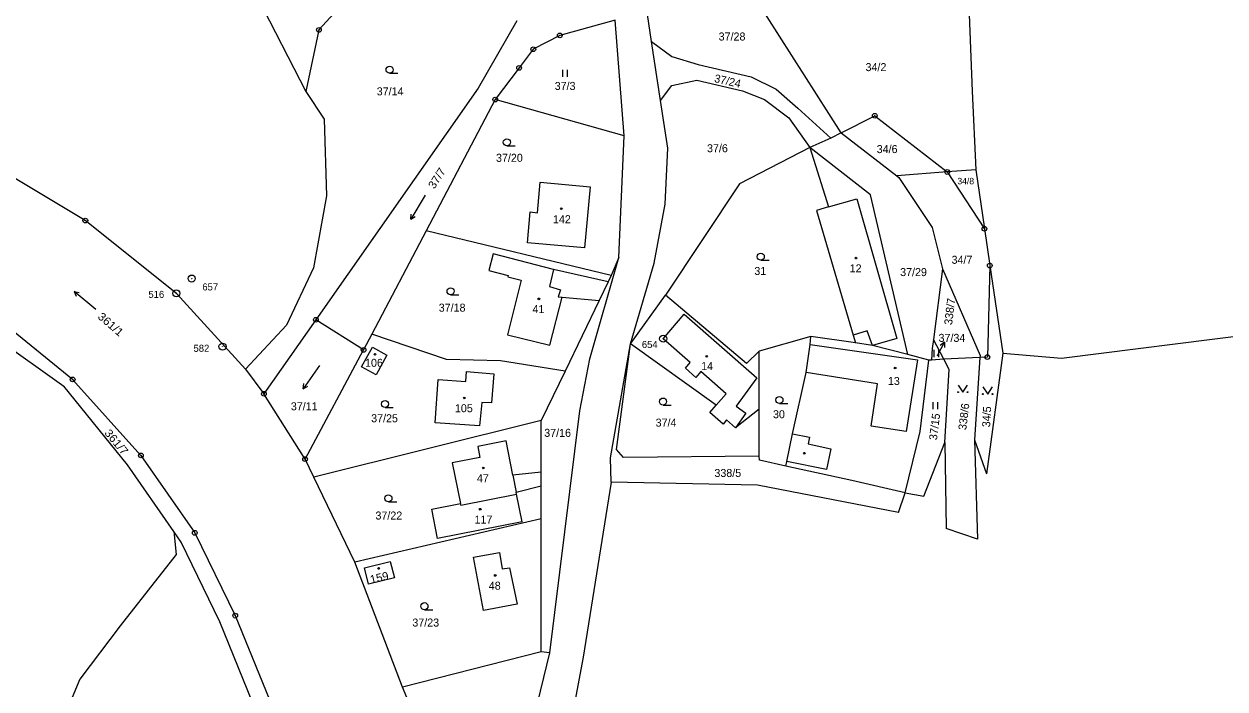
# Model space of a CAD drawing. Extents: x -645290 to -643454, y -1064771 to -1062356.
# Drawn here: x -644666.5 to -644411.4, y -1063973.1 to -1063831.9 of the extents above; entities that cross this region are included whole.
import ezdxf
from ezdxf.enums import TextEntityAlignment as Align

# ---------------------------------------------------------------- set-up
doc = ezdxf.new("R2010")
doc.units = 0
doc.header["$LTSCALE"] = 0.68
for name, color, linetype, lineweight in [('1', 7, 'Continuous', 25), ('3', 7, 'Continuous', 25), ('4', 7, 'Continuous', 13), ('5', 7, 'Continuous', 25), ('7', 7, 'Continuous', 13), ('8', 7, 'Continuous', 25)]:
    doc.layers.add(name, color=color, linetype=linetype, lineweight=lineweight)
doc.layers.add('2', color=7, linetype='Continuous')

msp = doc.modelspace()

# ---------------------------------------------------------------- linework, layer by layer
at = {"layer": '1'}
for p, q in [((-644575.96, -1063802.49), (-644603.81, -1063833.16)), ((-644627.33, -1063805.69), (-644606.6, -1063846.26)), ((-644492.88, -1063855.02), (-644514.22, -1063821.58)), ((-644466.06, -1063820.7), (-644465.03, -1063846.16)), ((-644533.14, -1063835.63), (-644534.01, -1063829.87)), ((-644561.79, -1063831.23), (-644569.98, -1063845.53)), ((-644540.88, -1063831.09), (-644552.65, -1063834.34)), ((-644538.96, -1063855.68), (-644540.88, -1063831.09)), ((-644603.81, -1063833.16), (-644606.6, -1063846.26)), ((-644552.65, -1063834.34), (-644558.27, -1063837.27)), ((-644558.27, -1063837.27), (-644561.29, -1063841.21)), ((-644531.25, -1063848.13), (-644533.14, -1063835.63)), ((-644533.14, -1063835.63), (-644528.83, -1063838.81)), ((-644528.83, -1063838.81), (-644523.29, -1063840.5)), ((-644561.29, -1063841.21), (-644566.37, -1063847.94)), ((-644523.29, -1063840.5), (-644512.02, -1063843.09)), ((-644531.25, -1063848.13), (-644528.83, -1063844.98)), ((-644528.83, -1063844.98), (-644523.54, -1063843.86)), ((-644523.54, -1063843.86), (-644513.81, -1063846.11)), ((-644512.02, -1063843.09), (-644506.66, -1063845.77)), ((-644606.6, -1063846.26), (-644602.72, -1063852.13)), ((-644569.98, -1063845.53), (-644604.46, -1063894.71)), ((-644566.37, -1063847.94), (-644581.03, -1063875.82)), ((-644538.96, -1063855.68), (-644566.37, -1063847.94)), ((-644513.81, -1063846.11), (-644509.15, -1063847.9)), ((-644509.15, -1063847.9), (-644504.01, -1063851.81)), ((-644506.66, -1063845.77), (-644502.07, -1063849.8)), ((-644465.03, -1063846.16), (-644464.3, -1063862.86)), ((-644529.72, -1063858.26), (-644531.25, -1063848.13)), ((-644502.07, -1063849.8), (-644495.11, -1063856.11)), ((-644602.72, -1063852.13), (-644602.19, -1063868.36)), ((-644504.01, -1063851.81), (-644499.57, -1063858.15)), ((-644540.1, -1063881.52), (-644538.96, -1063855.68)), ((-644492.88, -1063855.02), (-644495.11, -1063856.11)), ((-644492.88, -1063855.02), (-644481.08, -1063864.17)), ((-644499.57, -1063858.15), (-644514.49, -1063865.83)), ((-644495.11, -1063856.11), (-644499.57, -1063858.15)), ((-644486.65, -1063868.19), (-644499.57, -1063858.15)), ((-644499.57, -1063858.15), (-644495.55, -1063870.76)), ((-644530.24, -1063870.17), (-644529.72, -1063858.26)), ((-644653.43, -1063873.64), (-644671.61, -1063862.81)), ((-644470.36, -1063863.33), (-644481.08, -1063864.17)), ((-644464.3, -1063862.86), (-644470.36, -1063863.33)), ((-644470.36, -1063863.33), (-644462.46, -1063875.37)), ((-644464.3, -1063862.86), (-644462.46, -1063875.37)), ((-644556.8, -1063865.48), (-644546.19, -1063866.48)), ((-644514.49, -1063865.83), (-644530.22, -1063889.47)), ((-644602.19, -1063868.36), (-644604.98, -1063883.66)), ((-644546.19, -1063866.48), (-644547.38, -1063879.46)), ((-644478.75, -1063902.1), (-644486.65, -1063868.19)), ((-644532.59, -1063882.67), (-644530.24, -1063870.17)), ((-644495.55, -1063870.76), (-644498.09, -1063871.5)), ((-644559.52, -1063878.34), (-644558.91, -1063871.8)), ((-644498.09, -1063871.5), (-644490.36, -1063897.96)), ((-644634.09, -1063889.1), (-644653.43, -1063873.64)), ((-644581.03, -1063875.82), (-644592.55, -1063897.74)), ((-644541.7, -1063885.33), (-644581.03, -1063875.82)), ((-644462.46, -1063875.37), (-644461.31, -1063883.19)), ((-644547.38, -1063879.46), (-644559.52, -1063878.34)), ((-644566.81, -1063880.73), (-644567.71, -1063884.25)), ((-644553.98, -1063884.01), (-644566.81, -1063880.73)), ((-644604.98, -1063883.66), (-644610.67, -1063895.83)), ((-644546.25, -1063903.03), (-644540.1, -1063881.52)), ((-644540.1, -1063881.52), (-644541.7, -1063885.33)), ((-644537.63, -1063899.85), (-644532.59, -1063882.67)), ((-644461.31, -1063883.19), (-644458.57, -1063901.82)), ((-644567.71, -1063884.25), (-644563.64, -1063885.29)), ((-644563.64, -1063885.29), (-644563.71, -1063885.58)), ((-644563.71, -1063885.58), (-644560.87, -1063886.32)), ((-644542.36, -1063886.68), (-644553.98, -1063884.01)), ((-644541.7, -1063885.33), (-644542.36, -1063886.68)), ((-644471.38, -1063883.92), (-644473.27, -1063898.87)), ((-644471.38, -1063883.92), (-644463.37, -1063902.3)), ((-644560.87, -1063886.32), (-644563.73, -1063897.9)), ((-644542.36, -1063886.68), (-644544.27, -1063890.64)), ((-644619.42, -1063905.23), (-644634.09, -1063889.1)), ((-644554.79, -1063900.11), (-644552.17, -1063889.9)), ((-644552.17, -1063889.9), (-644544.27, -1063890.64)), ((-644544.27, -1063890.64), (-644551.54, -1063905.66)), ((-644537.63, -1063899.85), (-644530.22, -1063889.47)), ((-644512.98, -1063904.01), (-644530.22, -1063889.47)), ((-644656.12, -1063907.37), (-644671.86, -1063894.68)), ((-644610.67, -1063895.83), (-644619.42, -1063905.23)), ((-644604.46, -1063894.71), (-644615.5, -1063910.43)), ((-644594.32, -1063901.11), (-644604.46, -1063894.71)), ((-644673.62, -1063897.69), (-644657.97, -1063908.8)), ((-644592.55, -1063897.74), (-644594.32, -1063901.11)), ((-644576.74, -1063903.12), (-644592.55, -1063897.74)), ((-644563.73, -1063897.9), (-644554.79, -1063900.11)), ((-644499.35, -1063898.27), (-644510.33, -1063901.35)), ((-644499.47, -1063899.93), (-644499.35, -1063898.27)), ((-644489.87, -1063899.62), (-644499.35, -1063898.27)), ((-644490.36, -1063897.96), (-644489.87, -1063899.62)), ((-644471.09, -1063903.09), (-644473.27, -1063898.87)), ((-644446.1, -1063902.87), (-644404.58, -1063897.62)), ((-644606.74, -1063924.29), (-644594.32, -1063901.11)), ((-644594.74, -1063904.69), (-644592.43, -1063900.51)), ((-644592.43, -1063900.51), (-644589.37, -1063902.2)), ((-644541.87, -1063924.06), (-644537.63, -1063899.85)), ((-644540.57, -1063922.23), (-644537.63, -1063899.85)), ((-644519.44, -1063912.83), (-644537.63, -1063899.85)), ((-644510.33, -1063901.35), (-644512.98, -1063904.01)), ((-644510.33, -1063913.68), (-644510.33, -1063901.35)), ((-644500.33, -1063905.88), (-644499.47, -1063899.93)), ((-644486.2, -1063900.15), (-644489.87, -1063899.62)), ((-644478.75, -1063902.1), (-644486.2, -1063900.15)), ((-644589.37, -1063902.2), (-644591.68, -1063906.38)), ((-644565.21, -1063903.46), (-644576.74, -1063903.12)), ((-644551.54, -1063905.66), (-644565.21, -1063903.46)), ((-644548.36, -1063914.06), (-644546.25, -1063903.03)), ((-644474.26, -1063903.27), (-644478.75, -1063902.1)), ((-644476.07, -1063918.47), (-644474.26, -1063903.27)), ((-644473.68, -1063903.29), (-644474.26, -1063903.27)), ((-644471.09, -1063903.09), (-644473.68, -1063903.29)), ((-644463.4, -1063902.71), (-644471.09, -1063903.09)), ((-644469.95, -1063905.28), (-644471.09, -1063903.09)), ((-644463.4, -1063902.71), (-644464.59, -1063920.21)), ((-644463.37, -1063902.3), (-644463.4, -1063902.71)), ((-644458.57, -1063901.82), (-644462.03, -1063927.42)), ((-644458.57, -1063901.82), (-644446.1, -1063902.87)), ((-644619.42, -1063905.23), (-644615.5, -1063910.43)), ((-644591.68, -1063906.38), (-644594.74, -1063904.69)), ((-644572.63, -1063907.84), (-644572.48, -1063905.69)), ((-644572.48, -1063905.69), (-644566.68, -1063906.21)), ((-644566.68, -1063906.21), (-644567.15, -1063912.37)), ((-644551.54, -1063905.66), (-644556.6, -1063916.11)), ((-644503.22, -1063918.97), (-644500.33, -1063905.88)), ((-644470.87, -1063920.76), (-644469.95, -1063905.28)), ((-644644.48, -1063925.51), (-644657.97, -1063908.8)), ((-644641.61, -1063923.51), (-644656.12, -1063907.37)), ((-644579.14, -1063916.6), (-644578.49, -1063907.42)), ((-644578.49, -1063907.42), (-644572.63, -1063907.84)), ((-644606.74, -1063924.29), (-644615.5, -1063910.43)), ((-644569.19, -1063912.29), (-644569.69, -1063917.27)), ((-644567.15, -1063912.37), (-644569.19, -1063912.29)), ((-644554.73, -1063965.42), (-644548.36, -1063914.06)), ((-644520.8, -1063914.38), (-644519.44, -1063912.83)), ((-644510.33, -1063913.68), (-644515.32, -1063917.63)), ((-644510.33, -1063923.68), (-644510.33, -1063913.68)), ((-644556.6, -1063916.11), (-644604.88, -1063928.15)), ((-644569.69, -1063917.27), (-644579.14, -1063916.6)), ((-644556.6, -1063927.09), (-644556.6, -1063916.11)), ((-644517.94, -1063916.9), (-644520.8, -1063914.38)), ((-644517.25, -1063915.94), (-644517.94, -1063916.9)), ((-644515.32, -1063917.63), (-644517.25, -1063915.94)), ((-644504.42, -1063924.79), (-644503.22, -1063918.97)), ((-644479.27, -1063931.46), (-644476.07, -1063918.47)), ((-644564.06, -1063920.45), (-644570.04, -1063921.65)), ((-644570.04, -1063921.65), (-644569.6, -1063923.97)), ((-644562.63, -1063927.7), (-644564.06, -1063920.45)), ((-644475.33, -1063932.16), (-644470.87, -1063920.76)), ((-644470.87, -1063920.76), (-644470.6, -1063939.03)), ((-644464.59, -1063920.21), (-644463.9, -1063941.3)), ((-644464.59, -1063920.21), (-644462.03, -1063927.42)), ((-644641.61, -1063923.51), (-644630.18, -1063939.96)), ((-644604.88, -1063928.15), (-644606.74, -1063924.29)), ((-644569.6, -1063923.97), (-644575.52, -1063925.08)), ((-644541.7, -1063929.17), (-644541.87, -1063924.06)), ((-644539.12, -1063923.94), (-644540.57, -1063922.23)), ((-644510.33, -1063923.68), (-644539.12, -1063923.94)), ((-644510.23, -1063924.55), (-644510.33, -1063923.68)), ((-644504.63, -1063925.77), (-644510.23, -1063924.55)), ((-644634.62, -1063939.7), (-644644.48, -1063925.51)), ((-644575.52, -1063925.08), (-644573.77, -1063933.74)), ((-644556.6, -1063927.09), (-644562.63, -1063927.7)), ((-644556.6, -1063929.98), (-644556.6, -1063927.09)), ((-644504.63, -1063925.77), (-644504.42, -1063924.79)), ((-644490.58, -1063928.84), (-644504.63, -1063925.77)), ((-644596.19, -1063946.17), (-644604.88, -1063928.15)), ((-644541.7, -1063929.17), (-644547.65, -1063966.35)), ((-644510.64, -1063929.86), (-644541.7, -1063929.17)), ((-644479.27, -1063931.46), (-644490.58, -1063928.84)), ((-644573.69, -1063934.11), (-644561.82, -1063931.77)), ((-644561.92, -1063931.3), (-644556.6, -1063929.98)), ((-644561.82, -1063931.77), (-644561.92, -1063931.3)), ((-644560.66, -1063937.63), (-644561.82, -1063931.77)), ((-644556.59, -1063937.01), (-644556.6, -1063929.98)), ((-644480.67, -1063935.62), (-644510.64, -1063929.86)), ((-644480.67, -1063935.62), (-644479.27, -1063931.46)), ((-644479.27, -1063931.46), (-644475.33, -1063932.16)), ((-644579.82, -1063934.92), (-644573.77, -1063933.74)), ((-644573.69, -1063934.11), (-644573.77, -1063933.74)), ((-644556.59, -1063937.01), (-644596.19, -1063946.17)), ((-644578.61, -1063941.13), (-644579.82, -1063934.92)), ((-644556.6, -1063965.23), (-644556.59, -1063937.01)), ((-644634.62, -1063939.7), (-644634.12, -1063944.59)), ((-644633.06, -1063941.95), (-644634.62, -1063939.7)), ((-644560.66, -1063937.63), (-644578.61, -1063941.13)), ((-644463.9, -1063941.3), (-644470.6, -1063939.03)), ((-644624.84, -1063958.87), (-644633.06, -1063941.95)), ((-644630.18, -1063939.96), (-644621.6, -1063957.55)), ((-644634.12, -1063944.59), (-644646.05, -1063959.71)), ((-644570.97, -1063945.16), (-644565.48, -1063944.11)), ((-644565.48, -1063944.11), (-644564.88, -1063947.62)), ((-644586.08, -1063972.72), (-644596.19, -1063946.17)), ((-644594.13, -1063947.4), (-644588.66, -1063946.07)), ((-644593.25, -1063950.83), (-644594.13, -1063947.4)), ((-644588.66, -1063946.07), (-644587.76, -1063949.55)), ((-644568.87, -1063956.42), (-644570.97, -1063945.16)), ((-644564.88, -1063947.62), (-644563.3, -1063947.42)), ((-644563.3, -1063947.42), (-644561.73, -1063955.08)), ((-644587.76, -1063949.55), (-644593.25, -1063950.83)), ((-644561.73, -1063955.08), (-644568.87, -1063956.42)), ((-644621.6, -1063957.55), (-644613.6, -1063977.09)), ((-644646.05, -1063959.71), (-644654.6, -1063971.04)), ((-644616.95, -1063978.39), (-644624.84, -1063958.87)), ((-644556.6, -1063965.23), (-644586.08, -1063972.72)), ((-644554.73, -1063965.42), (-644556.6, -1063965.23)), ((-644559.44, -1063984.36), (-644554.73, -1063965.42)), ((-644547.65, -1063966.35), (-644549.67, -1063976.91)), ((-644654.6, -1063971.04), (-644661.51, -1063987.36)), ((-644581.25, -1063984.25), (-644586.08, -1063972.72))]:
    msp.add_line(p, q, dxfattribs=at)
for points in [[(-644492.88, -1063855.02), (-644485.74, -1063851.39), (-644470.36, -1063863.33)], [(-644558.91, -1063871.8), (-644557.41, -1063871.98), (-644556.8, -1063865.48)], [(-644481.08, -1063864.17), (-644480.66, -1063864.49), (-644473.56, -1063875.12), (-644471.38, -1063883.92)], [(-644461.31, -1063883.19), (-644461.82, -1063902.63), (-644463.4, -1063902.71)], [(-644473.27, -1063898.87), (-644473.52, -1063900.81), (-644473.68, -1063903.29)]]:
    msp.add_lwpolyline(points, dxfattribs=at)
at = {"layer": '3'}
for p, q in [((-644588.803, -1063842.36), (-644587.053, -1063842.36)), ((-644552.011, -1063843.11), (-644552.011, -1063841.61)), ((-644551.01, -1063843.11), (-644551.01, -1063841.61)), ((-644563.893, -1063857.77), (-644562.143, -1063857.77)), ((-644584.301, -1063873.382), (-644584.228, -1063872.286)), ((-644509.953, -1063882.07), (-644508.203, -1063882.07)), ((-644655.786, -1063888.704), (-644654.715, -1063888.948)), ((-644575.853, -1063889.41), (-644574.103, -1063889.41)), ((-644473.141, -1063902.63), (-644473.141, -1063901.13)), ((-644472.14, -1063902.63), (-644472.14, -1063901.13)), ((-644607.158, -1063909.357), (-644607.008, -1063908.269)), ((-644589.763, -1063913.35), (-644588.013, -1063913.35)), ((-644530.713, -1063912.83), (-644528.963, -1063912.83)), ((-644505.993, -1063912.5), (-644504.243, -1063912.5)), ((-644473.331, -1063913.71), (-644473.331, -1063912.21)), ((-644472.33, -1063913.71), (-644472.33, -1063912.21)), ((-644589.043, -1063933.38), (-644587.293, -1063933.38)), ((-644581.393, -1063956.29), (-644579.643, -1063956.29))]:
    msp.add_line(p, q, dxfattribs=at)
for points in [[(-644581.211, -1063868.239), (-644584.301, -1063873.382), (-644583.368, -1063872.802)], [(-644651.189, -1063892.561), (-644655.786, -1063888.704), (-644655.36, -1063889.716)], [(-644603.716, -1063904.442), (-644607.158, -1063909.357), (-644606.186, -1063908.844)], [(-644468.04, -1063908.589), (-644467.04, -1063910.09), (-644466.04, -1063908.589)], [(-644462.76, -1063908.979), (-644461.76, -1063910.48), (-644460.76, -1063908.979)]]:
    msp.add_lwpolyline(points, dxfattribs=at)
for centre, radius in [((-644588.8029, -1063841.6098), 0.75), ((-644563.8929, -1063857.0198), 0.75), ((-644509.9529, -1063881.3198), 0.75), ((-644575.8529, -1063888.6598), 0.75), ((-644530.7129, -1063912.0798), 0.75), ((-644505.9929, -1063911.7498), 0.75), ((-644468.04, -1063910.0895), 0.1), ((-644466.04, -1063910.0895), 0.1), ((-644462.76, -1063910.4795), 0.1), ((-644460.76, -1063910.4795), 0.1), ((-644589.7629, -1063912.5998), 0.75), ((-644589.0429, -1063932.6298), 0.75), ((-644581.3929, -1063955.5398), 0.75)]:
    msp.add_circle(centre, radius, dxfattribs=at)
at = {"layer": '4'}
for p, q in [((-644495.55, -1063870.76), (-644489.54, -1063869.02)), ((-644489.54, -1063869.02), (-644481.08, -1063898.69)), ((-644553.98, -1063884.01), (-644554.81, -1063887.64)), ((-644554.81, -1063887.64), (-644552.52, -1063888.32)), ((-644552.52, -1063888.32), (-644552.96, -1063889.83)), ((-644552.96, -1063889.83), (-644552.17, -1063889.9)), ((-644530.69, -1063898.74), (-644526.21, -1063893.51)), ((-644526.21, -1063893.51), (-644510.8, -1063907.03)), ((-644524.97, -1063903.77), (-644530.69, -1063898.74)), ((-644487.37, -1063897.08), (-644490.36, -1063897.96)), ((-644486.2, -1063900.15), (-644487.37, -1063897.08)), ((-644481.08, -1063898.69), (-644486.2, -1063900.15)), ((-644499.47, -1063899.93), (-644476.69, -1063903.22)), ((-644525.98, -1063905.02), (-644524.97, -1063903.77)), ((-644476.69, -1063903.22), (-644479.06, -1063918.44)), ((-644523.77, -1063907), (-644525.98, -1063905.02)), ((-644522.72, -1063905.73), (-644523.77, -1063907)), ((-644517.32, -1063910.43), (-644522.72, -1063905.73)), ((-644485.14, -1063908.33), (-644500.33, -1063905.88)), ((-644510.8, -1063907.03), (-644515.15, -1063913.04)), ((-644486.51, -1063917.3), (-644485.14, -1063908.33)), ((-644519.44, -1063912.83), (-644517.32, -1063910.43)), ((-644515.15, -1063913.04), (-644513.11, -1063914.52)), ((-644513.11, -1063914.52), (-644515.32, -1063917.63)), ((-644503.22, -1063918.97), (-644499.6, -1063919.61)), ((-644479.06, -1063918.44), (-644486.51, -1063917.3)), ((-644499.6, -1063919.61), (-644499.92, -1063921.03)), ((-644499.92, -1063921.03), (-644495.06, -1063922.09)), ((-644495.06, -1063922.09), (-644496.01, -1063926.51)), ((-644496.01, -1063926.51), (-644504.42, -1063924.79)), ((-644562.63, -1063927.7), (-644561.92, -1063931.3))]:
    msp.add_line(p, q, dxfattribs=at)
at = {"layer": '5'}
for centre in [(-644552.3368, -1063871.1192), (-644489.7268, -1063881.6192), (-644557.0968, -1063890.2692), (-644591.8868, -1063902.0392), (-644521.4368, -1063902.4692), (-644481.4168, -1063904.9692), (-644572.9368, -1063911.3192), (-644500.7168, -1063923.0492), (-644568.8968, -1063926.1892), (-644569.5568, -1063934.9492), (-644591.1368, -1063947.5192), (-644566.3668, -1063949.0092)]:
    msp.add_circle(centre, 0.175, dxfattribs=at)
at = {"layer": '7'}
msp.add_line((-644470.911, -1063899.5), (-644471.823, -1063900.149), dxfattribs=at)
msp.add_lwpolyline([(-644472.44, -1063902.37), (-644472.32, -1063902.15), (-644470.911, -1063899.5), (-644470.939, -1063900.62)], dxfattribs=at)
at = {"layer": '8'}
for centre, radius in [((-644603.81, -1063833.1599), 0.5), ((-644603.81, -1063833.1599), 0.0303), ((-644552.65, -1063834.3399), 0.5), ((-644552.65, -1063834.3399), 0.0303), ((-644558.27, -1063837.2699), 0.5), ((-644558.27, -1063837.2699), 0.0303), ((-644561.29, -1063841.2099), 0.5), ((-644561.29, -1063841.2099), 0.0303), ((-644566.37, -1063847.9399), 0.5), ((-644566.37, -1063847.9399), 0.0303), ((-644485.74, -1063851.3899), 0.5), ((-644485.74, -1063851.3899), 0.0303), ((-644470.36, -1063863.3299), 0.5), ((-644470.36, -1063863.3299), 0.0303), ((-644653.43, -1063873.6399), 0.5), ((-644653.43, -1063873.6399), 0.0303), ((-644462.46, -1063875.3699), 0.5), ((-644462.46, -1063875.3699), 0.0303), ((-644461.31, -1063883.1899), 0.5), ((-644461.31, -1063883.1899), 0.0303), ((-644630.83, -1063885.9598), 0.75), ((-644630.83, -1063885.9598), 0.03), ((-644634.09, -1063889.0998), 0.75), ((-644634.09, -1063889.0998), 0.03), ((-644604.46, -1063894.7099), 0.5), ((-644604.46, -1063894.7099), 0.0303), ((-644530.69, -1063898.7398), 0.75), ((-644530.69, -1063898.7398), 0.03), ((-644624.29, -1063900.4098), 0.75), ((-644624.29, -1063900.4098), 0.03), ((-644594.32, -1063901.1099), 0.5), ((-644594.32, -1063901.1099), 0.0303), ((-644461.82, -1063902.6299), 0.5), ((-644461.82, -1063902.6299), 0.0303), ((-644656.12, -1063907.3699), 0.5), ((-644656.12, -1063907.3699), 0.0303), ((-644615.5, -1063910.4299), 0.5), ((-644615.5, -1063910.4299), 0.0303), ((-644641.61, -1063923.5099), 0.5), ((-644641.61, -1063923.5099), 0.0303), ((-644606.74, -1063924.2899), 0.5), ((-644606.74, -1063924.2899), 0.0303), ((-644630.18, -1063939.9599), 0.5), ((-644630.18, -1063939.9599), 0.0303), ((-644621.6, -1063957.5499), 0.5), ((-644621.6, -1063957.5499), 0.0303)]:
    msp.add_circle(centre, radius, dxfattribs=at)

# ---------------------------------------------------------------- texts
at = {"layer": '2'}
for s, height, p in [('37/28', 1.7, (-644516.06, -1063835.405)), ('34/2', 1.7, (-644485.489, -1063841.905)), ('37/14', 1.7, (-644588.69, -1063847.054)), ('37/3', 1.7, (-644551.519, -1063845.905)), ('37/6', 1.7, (-644519.159, -1063859.135)), ('34/6', 1.7, (-644483.119, -1063859.314)), ('37/20', 1.7, (-644563.35, -1063861.165)), ('34/8', 1.36, (-644466.419, -1063865.94)), ('34/7', 1.7, (-644467.219, -1063882.824)), ('31', 1.7, (-644510.059, -1063885.195)), ('12', 1.7, (-644489.819, -1063884.645)), ('37/29', 1.7, (-644477.51, -1063885.435)), ('37/18', 1.7, (-644575.52, -1063892.985)), ('41', 1.7, (-644557.189, -1063893.295)), ('37/34', 1.7, (-644469.35, -1063899.405)), ('106', 1.7, (-644592.119, -1063904.705)), ('14', 1.7, (-644521.359, -1063905.395)), ('13', 1.7, (-644481.689, -1063908.564)), ('37/11', 1.7, (-644606.93, -1063913.935)), ('105', 1.7, (-644573.029, -1063914.344)), ('30', 1.7, (-644506.099, -1063915.625)), ('37/25', 1.7, (-644589.87, -1063916.475)), ('37/4', 1.7, (-644530.079, -1063917.405)), ('37/16', 1.7, (-644553.11, -1063919.574)), ('338/5', 1.7, (-644516.96, -1063928.094)), ('47', 1.7, (-644568.989, -1063929.215)), ('37/22', 1.7, (-644588.96, -1063937.135)), ('48', 1.7, (-644566.469, -1063952.035)), ('37/23', 1.7, (-644581.12, -1063959.865))]:
    msp.add_text(s, height=height, dxfattribs=at).set_placement(p, align=Align.CENTER)
for s, rotation, p in [('37/24', 347, (-644517.1882, -1063844.8365)), ('338/7', 83, (-644468.9809, -1063893.0581)), ('37/15', 83, (-644472.2009, -1063917.5281))]:
    msp.add_text(s, height=1.7, rotation=rotation, dxfattribs=at).set_placement(p, align=Align.CENTER)
for s, rotation, width, p in [('37/7', 57, 1.05, (-644578.0496, -1063865.1154)), ('361/1', 319, 1.1, (-644648.5846, -1063896.3175)), ('159', 13, 1.05, (-644590.8062, -1063950.2912))]:
    msp.add_text(s, height=1.7, rotation=rotation, dxfattribs=dict(at, width=width)).set_placement(p, align=Align.CENTER)
for s, p in [('142', (-644554.1, -1063874.205)), ('117', (-644570.76, -1063938.005))]:
    msp.add_text(s, height=1.7, dxfattribs=at).set_placement(p)
for s, rotation, p in [('338/6', 83, (-644466.328, -1063918.211)), ('34/5', 87, (-644461.245, -1063917.572))]:
    msp.add_text(s, height=1.7, rotation=rotation, dxfattribs=at).set_placement(p)
at = {"layer": '2', "width": 1.1}
msp.add_text('361/7', height=1.7, rotation=310, dxfattribs=at).set_placement((-644649.485, -1063918.823))
at = {"layer": '8'}
for s, p in [('516', (-644636.679, -1063890.067)), ('582', (-644627.099, -1063901.517))]:
    msp.add_text(s, height=1.5, dxfattribs=at).set_placement(p, align=Align.RIGHT)
for s, p in [('657', (-644628.57, -1063888.485)), ('654', (-644535.21, -1063900.705))]:
    msp.add_text(s, height=1.5, dxfattribs=at).set_placement(p)

doc.saveas('drawing.dxf')
